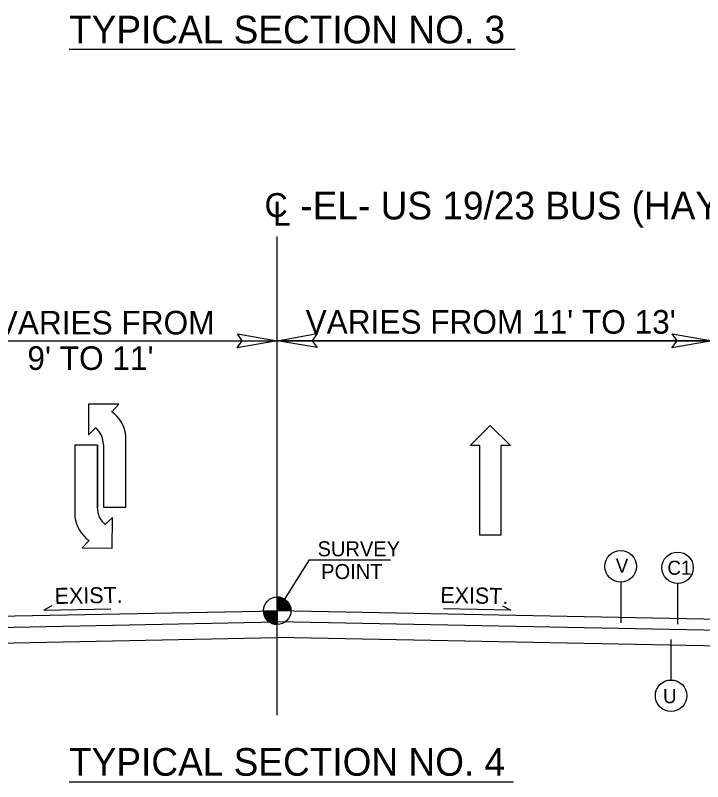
# Model space of a CAD drawing. Extents: x 1022283 to 1026986, y 174822 to 180471.
# Drawn here: x 1023630 to 1024096, y 178406 to 178925 of the extents above; entities that cross this region are included whole.
import ezdxf

# ---------------------------------------------------------------- set-up
doc = ezdxf.new("R2010")
doc.units = 0
for name, color, linetype in [('Default', 7, 'Continuous'), ('Prop Dimension', 7, 'Continuous'), ('Prop Lane Arrow CELL', 7, 'Continuous'), ('Prop Terminator CELL', 7, 'Continuous'), ('Typical Berm Information CELL', 7, 'Continuous'), ('Typical Grade Point Symbol CELL', 7, 'Continuous'), ('Typical ID Circle CELL', 7, 'Continuous'), ('Typical Text Centerline CELL', 7, 'Continuous'), ('Typical Text Grade Point CELL', 7, 'Continuous'), ('Typical Text ID Circle CELL', 7, 'Continuous'), ('Typical Text Label CELL', 7, 'Continuous')]:
    doc.layers.add(name, color=color, linetype=linetype)

# ---------------------------------------------------------------- blocks, each defined once
blk = doc.blocks.new('Lane Arrow Through')
at = {"layer": 'Prop Lane Arrow CELL'}
for p, q in [((-3.15, 1.6), (-3.15, 3.1)), ((-3.15, 3.1), (0, 0)), ((-17.15, 1.6), (-3.15, 1.6)), ((-17.15, -1.7), (-17.15, 1.6)), ((0, 0), (-3.15, -3.2)), ((-3.15, -1.7), (-17.15, -1.7)), ((-3.15, -3.2), (-3.15, -1.7))]:
    blk.add_line(p, q, dxfattribs=at)

msp = doc.modelspace()

# ---------------------------------------------------------------- linework, layer by layer
at = {"layer": 'Default'}
for p, q in [((1023299.79, 178705.04), (1023807.5, 178705.04)), ((1023807.5, 178705.04), (1024315.21, 178705.04)), ((1024315.21, 178705.04), (1023807.5, 178705.04))]:
    msp.add_line(p, q, dxfattribs=at)
at = {"layer": 'Prop Dimension'}
for p, q in [((1023807.5, 178716.15), (1023807.5, 178775.61)), ((1023807.5, 178451.35), (1023807.5, 178716.15)), ((1023829.15, 178556.58), (1023807.5, 178522.14)), ((1023829.15, 178556.58), (1023807.5, 178522.14)), ((1023299.79, 178511.99), (1023807.5, 178522.14)), ((1023299.79, 178511.99), (1023807.5, 178522.14)), ((1024315.21, 178511.99), (1023807.5, 178522.14)), ((1024315.21, 178511.99), (1023807.5, 178522.14)), ((1023299.79, 178504.49), (1023807.5, 178514.64)), ((1023299.79, 178504.49), (1023807.5, 178514.64)), ((1024315.21, 178504.49), (1023807.5, 178514.64)), ((1024315.21, 178504.49), (1023807.5, 178514.64)), ((1023299.79, 178493.9), (1023807.5, 178504.06)), ((1024315.21, 178493.9), (1023807.5, 178504.06))]:
    msp.add_line(p, q, dxfattribs=at)
at = {"layer": 'Prop Lane Arrow CELL'}
for p, q in [((1023700.21, 178662.05), (1023679.66, 178662.05)), ((1023679.66, 178662.05), (1023679.66, 178641.27)), ((1023695.37, 178656.97), (1023700.21, 178662.05)), ((1023679.66, 178641.27), (1023684.51, 178646.11)), ((1023705.06, 178592.32), (1023705.06, 178641.04)), ((1023670.43, 178634.34), (1023670.43, 178585.62)), ((1023685.67, 178634.34), (1023670.43, 178634.34)), ((1023685.67, 178592.09), (1023685.67, 178634.34)), ((1023685.67, 178634.34), (1023685.67, 178592.09)), ((1023689.82, 178634.57), (1023689.82, 178592.32)), ((1023689.82, 178592.32), (1023705.06, 178592.32)), ((1023695.83, 178585.39), (1023690.98, 178580.54)), ((1023695.6, 178564.61), (1023695.83, 178585.39)), ((1023680.13, 178569.69), (1023675.28, 178564.84)), ((1023675.28, 178564.84), (1023695.6, 178564.61))]:
    msp.add_line(p, q, dxfattribs=at)
for centre, radius, start, end in [((1023681.03, 178637.44), 24.26, 8.6761, 53.9878), ((1023674.65, 178634.68), 15.12, 360, 49.6582), ((1023700.71, 178592.04), 15.12, 180, 229.6582), ((1023694.33, 178589.28), 24.26, 188.6761, 233.9878)]:
    msp.add_arc(centre, radius, start, end, dxfattribs=at)
at = {"layer": 'Prop Terminator CELL'}
for points in [[(1023780.5, 178709.69), (1023807.5, 178705.04), (1023780.35, 178700.24), (1023783.8, 178705.04)], [(1023834.5, 178700.39), (1023807.5, 178705.04), (1023834.65, 178709.84), (1023831.2, 178705.04)], [(1023834.5, 178700.39), (1023807.5, 178705.04), (1023834.65, 178709.84), (1023831.2, 178705.04)], [(1024075.03, 178709.69), (1024102.03, 178705.04), (1024074.88, 178700.24), (1024078.33, 178705.04)]]:
    msp.add_lwpolyline(points, close=True, dxfattribs=at)
at = {"layer": 'Typical Berm Information CELL'}
for p, q in [((1023654.85, 178525.35), (1023649.33, 178522.59)), ((1023649.33, 178522.59), (1023694.85, 178523.5)), ((1023965.68, 178522.59), (1023920.16, 178523.5)), ((1023960.16, 178525.35), (1023965.68, 178522.59))]:
    msp.add_line(p, q, dxfattribs=at)
at = {"layer": 'Typical Grade Point Symbol CELL'}
for p, q in [((1023807.5, 178522.14), (1023807.5, 178531.44)), ((1023807.5, 178522.14), (1023807.5, 178531.44)), ((1023798.21, 178522.14), (1023807.5, 178522.14)), ((1023798.21, 178522.14), (1023807.5, 178522.14)), ((1023807.48, 178512.85), (1023807.5, 178522.14)), ((1023807.5, 178522.14), (1023807.48, 178512.85)), ((1023807.48, 178512.85), (1023807.5, 178522.14)), ((1023807.5, 178522.14), (1023807.48, 178512.85)), ((1023816.8, 178522.14), (1023807.5, 178522.14)), ((1023816.8, 178522.14), (1023807.5, 178522.14))]:
    msp.add_line(p, q, dxfattribs=at)
for points in [[(1023807.59, 178531.44), (1023807.59, 178531.44), (1023807.59, 178522.14)], [(1023807.59, 178531.44), (1023807.59, 178531.44), (1023807.59, 178522.14)], [(1023807.77, 178531.44), (1023807.77, 178522.14)], [(1023807.77, 178531.44), (1023807.77, 178522.14)], [(1023807.96, 178531.42), (1023807.96, 178522.14)], [(1023807.96, 178531.42), (1023807.96, 178522.14)], [(1023808.14, 178531.42), (1023808.14, 178522.14)], [(1023808.14, 178531.42), (1023808.14, 178522.14)], [(1023808.33, 178531.4), (1023808.33, 178522.14)], [(1023808.33, 178531.4), (1023808.33, 178522.14)], [(1023808.52, 178531.38), (1023808.52, 178522.14)], [(1023808.52, 178531.38), (1023808.52, 178522.14)], [(1023808.7, 178531.36), (1023808.7, 178522.14)], [(1023808.7, 178531.36), (1023808.7, 178522.14)], [(1023808.89, 178531.34), (1023808.89, 178522.14)], [(1023808.89, 178531.34), (1023808.89, 178522.14)], [(1023809.07, 178531.32), (1023809.07, 178522.14)], [(1023809.07, 178531.32), (1023809.07, 178522.14)], [(1023809.26, 178531.27), (1023809.26, 178522.14)], [(1023809.26, 178531.27), (1023809.26, 178522.14)], [(1023809.45, 178531.23), (1023809.45, 178522.14)], [(1023809.45, 178531.23), (1023809.45, 178522.14)], [(1023809.63, 178531.19), (1023809.63, 178522.14)], [(1023809.63, 178531.19), (1023809.63, 178522.14)], [(1023809.82, 178531.15), (1023809.82, 178522.14)], [(1023809.82, 178531.15), (1023809.82, 178522.14)], [(1023810, 178531.09), (1023810, 178522.14)], [(1023810, 178531.09), (1023810, 178522.14)], [(1023810.19, 178531.05), (1023810.19, 178522.14)], [(1023810.19, 178531.05), (1023810.19, 178522.14)], [(1023810.38, 178530.98), (1023810.38, 178522.14)], [(1023810.38, 178530.98), (1023810.38, 178522.14)], [(1023810.56, 178530.92), (1023810.56, 178522.14)], [(1023810.56, 178530.92), (1023810.56, 178522.14)], [(1023810.75, 178530.86), (1023810.75, 178522.14)], [(1023810.75, 178530.86), (1023810.75, 178522.14)], [(1023810.93, 178530.78), (1023810.93, 178522.14)], [(1023810.93, 178530.78), (1023810.93, 178522.14)], [(1023811.12, 178530.7), (1023811.12, 178522.14)], [(1023811.12, 178530.7), (1023811.12, 178522.14)], [(1023811.31, 178530.61), (1023811.31, 178522.14)], [(1023811.31, 178530.61), (1023811.31, 178522.14)], [(1023811.49, 178530.53), (1023811.49, 178522.14)], [(1023811.49, 178530.53), (1023811.49, 178522.14)], [(1023811.68, 178530.45), (1023811.68, 178522.14)], [(1023811.68, 178530.45), (1023811.68, 178522.14)], [(1023811.86, 178530.34), (1023811.86, 178522.14)], [(1023811.86, 178530.34), (1023811.86, 178522.14)], [(1023812.05, 178530.24), (1023812.05, 178522.14)], [(1023812.05, 178530.24), (1023812.05, 178522.14)], [(1023812.23, 178530.14), (1023812.23, 178522.14)], [(1023812.23, 178530.14), (1023812.23, 178522.14)], [(1023812.42, 178530.04), (1023812.42, 178522.14)], [(1023812.42, 178530.04), (1023812.42, 178522.14)], [(1023812.61, 178529.91), (1023812.61, 178522.14)], [(1023812.61, 178529.91), (1023812.61, 178522.14)], [(1023812.79, 178529.79), (1023812.79, 178522.14)], [(1023812.79, 178529.79), (1023812.79, 178522.14)], [(1023812.98, 178529.64), (1023812.98, 178522.14)], [(1023812.98, 178529.64), (1023812.98, 178522.14)], [(1023813.16, 178529.52), (1023813.16, 178522.14)], [(1023813.16, 178529.52), (1023813.16, 178522.14)], [(1023813.35, 178529.37), (1023813.35, 178522.14)], [(1023813.35, 178529.37), (1023813.35, 178522.14)], [(1023813.54, 178529.21), (1023813.54, 178522.14)], [(1023813.54, 178529.21), (1023813.54, 178522.14)], [(1023813.72, 178529.04), (1023813.72, 178522.14)], [(1023813.72, 178529.04), (1023813.72, 178522.14)], [(1023813.91, 178528.88), (1023813.91, 178522.14)], [(1023813.91, 178528.88), (1023813.91, 178522.14)], [(1023814.09, 178528.69), (1023814.09, 178522.14)], [(1023814.09, 178528.69), (1023814.09, 178522.14)], [(1023814.28, 178528.51), (1023814.28, 178522.14)], [(1023814.28, 178528.51), (1023814.28, 178522.14)], [(1023814.47, 178528.3), (1023814.47, 178522.14)], [(1023814.47, 178528.3), (1023814.47, 178522.14)], [(1023814.65, 178528.07), (1023814.65, 178522.14)], [(1023814.65, 178528.07), (1023814.65, 178522.14)], [(1023814.84, 178527.85), (1023814.84, 178522.14)], [(1023814.84, 178527.85), (1023814.84, 178522.14)], [(1023815.02, 178527.6), (1023815.02, 178522.14)], [(1023815.02, 178527.6), (1023815.02, 178522.14)], [(1023815.21, 178527.33), (1023815.21, 178522.14)], [(1023815.21, 178527.33), (1023815.21, 178522.14)], [(1023815.4, 178527.04), (1023815.4, 178522.14)], [(1023815.4, 178527.04), (1023815.4, 178522.14)], [(1023798.25, 178522.14), (1023798.25, 178521.13)], [(1023798.25, 178522.14), (1023798.25, 178521.13)], [(1023798.44, 178522.14), (1023798.44, 178520.04)], [(1023798.44, 178522.14), (1023798.44, 178520.04)], [(1023798.62, 178522.14), (1023798.62, 178519.38)], [(1023798.62, 178522.14), (1023798.62, 178519.38)], [(1023798.81, 178522.14), (1023798.81, 178518.82)], [(1023798.81, 178522.14), (1023798.81, 178518.82)], [(1023798.99, 178522.14), (1023798.99, 178518.38)], [(1023798.99, 178522.14), (1023798.99, 178518.38)], [(1023799.18, 178522.14), (1023799.18, 178517.99)], [(1023799.18, 178522.14), (1023799.18, 178517.99)], [(1023799.37, 178522.14), (1023799.37, 178517.64)], [(1023799.37, 178522.14), (1023799.37, 178517.64)], [(1023799.55, 178522.14), (1023799.55, 178517.31)], [(1023799.55, 178522.14), (1023799.55, 178517.31)], [(1023799.74, 178522.14), (1023799.74, 178517.02)], [(1023799.74, 178522.14), (1023799.74, 178517.02)], [(1023799.92, 178522.14), (1023799.92, 178516.75)], [(1023799.92, 178522.14), (1023799.92, 178516.75)], [(1023800.11, 178522.14), (1023800.11, 178516.5)], [(1023800.11, 178522.14), (1023800.11, 178516.5)], [(1023800.3, 178522.14), (1023800.3, 178516.28)], [(1023800.3, 178522.14), (1023800.3, 178516.28)], [(1023800.48, 178522.14), (1023800.48, 178516.05)], [(1023800.48, 178522.14), (1023800.48, 178516.05)], [(1023800.67, 178522.14), (1023800.67, 178515.84)], [(1023800.67, 178522.14), (1023800.67, 178515.84)], [(1023800.85, 178522.14), (1023800.85, 178515.64)], [(1023800.85, 178522.14), (1023800.85, 178515.64)], [(1023801.04, 178522.14), (1023801.04, 178515.45)], [(1023801.04, 178522.14), (1023801.04, 178515.45)], [(1023801.23, 178522.14), (1023801.23, 178515.29)], [(1023801.23, 178522.14), (1023801.23, 178515.29)], [(1023801.41, 178522.14), (1023801.41, 178515.12)], [(1023801.41, 178522.14), (1023801.41, 178515.12)], [(1023801.6, 178522.14), (1023801.6, 178514.96)], [(1023801.6, 178522.14), (1023801.6, 178514.96)], [(1023801.78, 178522.14), (1023801.78, 178514.81)], [(1023801.78, 178522.14), (1023801.78, 178514.81)], [(1023801.97, 178522.14), (1023801.97, 178514.67)], [(1023801.97, 178522.14), (1023801.97, 178514.67)], [(1023802.15, 178522.14), (1023802.15, 178514.54)], [(1023802.15, 178522.14), (1023802.15, 178514.54)], [(1023802.34, 178522.14), (1023802.34, 178514.42)], [(1023802.34, 178522.14), (1023802.34, 178514.42)], [(1023802.53, 178522.14), (1023802.53, 178514.29)], [(1023802.53, 178522.14), (1023802.53, 178514.29)], [(1023802.71, 178522.14), (1023802.71, 178514.17)], [(1023802.71, 178522.14), (1023802.71, 178514.17)], [(1023802.9, 178522.14), (1023802.9, 178514.07)], [(1023802.9, 178522.14), (1023802.9, 178514.07)], [(1023803.08, 178522.14), (1023803.08, 178513.96)], [(1023803.08, 178522.14), (1023803.08, 178513.96)], [(1023803.27, 178522.14), (1023803.27, 178513.86)], [(1023803.27, 178522.14), (1023803.27, 178513.86)], [(1023803.46, 178522.14), (1023803.46, 178513.78)], [(1023803.46, 178522.14), (1023803.46, 178513.78)], [(1023803.64, 178522.14), (1023803.64, 178513.7)], [(1023803.64, 178522.14), (1023803.64, 178513.7)], [(1023803.83, 178522.14), (1023803.83, 178513.61)], [(1023803.83, 178522.14), (1023803.83, 178513.61)], [(1023804.01, 178522.14), (1023804.01, 178513.53)], [(1023804.01, 178522.14), (1023804.01, 178513.53)], [(1023804.2, 178522.14), (1023804.2, 178513.45)], [(1023804.2, 178522.14), (1023804.2, 178513.45)], [(1023804.39, 178522.14), (1023804.39, 178513.39)], [(1023804.39, 178522.14), (1023804.39, 178513.39)], [(1023804.57, 178522.14), (1023804.57, 178513.32)], [(1023804.57, 178522.14), (1023804.57, 178513.32)], [(1023804.76, 178522.14), (1023804.76, 178513.26)], [(1023804.76, 178522.14), (1023804.76, 178513.26)], [(1023804.94, 178522.14), (1023804.94, 178513.22)], [(1023804.94, 178522.14), (1023804.94, 178513.22)], [(1023805.13, 178522.14), (1023805.13, 178513.16)], [(1023805.13, 178522.14), (1023805.13, 178513.16)], [(1023805.32, 178522.14), (1023805.32, 178513.12)], [(1023805.32, 178522.14), (1023805.32, 178513.12)], [(1023805.5, 178522.14), (1023805.5, 178513.08)], [(1023805.5, 178522.14), (1023805.5, 178513.08)], [(1023805.69, 178522.14), (1023805.69, 178513.03)], [(1023805.69, 178522.14), (1023805.69, 178513.03)], [(1023805.87, 178522.14), (1023805.87, 178512.99)], [(1023805.87, 178522.14), (1023805.87, 178512.99)], [(1023806.06, 178522.14), (1023806.06, 178512.97)], [(1023806.06, 178522.14), (1023806.06, 178512.97)], [(1023806.24, 178522.14), (1023806.24, 178512.93)], [(1023806.24, 178522.14), (1023806.24, 178512.93)], [(1023806.43, 178522.14), (1023806.43, 178512.91)], [(1023806.43, 178522.14), (1023806.43, 178512.91)], [(1023806.62, 178522.14), (1023806.62, 178512.89)], [(1023806.62, 178522.14), (1023806.62, 178512.89)], [(1023806.8, 178522.14), (1023806.8, 178512.87)], [(1023806.8, 178522.14), (1023806.8, 178512.87)], [(1023806.99, 178522.14), (1023806.99, 178512.87)], [(1023806.99, 178522.14), (1023806.99, 178512.87)], [(1023807.17, 178522.14), (1023807.17, 178512.85)], [(1023807.17, 178522.14), (1023807.17, 178512.85)], [(1023807.36, 178522.14), (1023807.36, 178512.85), (1023807.36, 178512.85)], [(1023807.36, 178522.14), (1023807.36, 178512.85), (1023807.36, 178512.85)], [(1023815.58, 178526.73), (1023815.58, 178522.14)], [(1023815.58, 178526.73), (1023815.58, 178522.14)], [(1023815.77, 178526.4), (1023815.77, 178522.14)], [(1023815.77, 178526.4), (1023815.77, 178522.14)], [(1023815.95, 178526.01), (1023815.95, 178522.14)], [(1023815.95, 178526.01), (1023815.95, 178522.14)], [(1023816.14, 178525.57), (1023816.14, 178522.14)], [(1023816.14, 178525.57), (1023816.14, 178522.14)], [(1023816.32, 178525.06), (1023816.32, 178522.14)], [(1023816.32, 178525.06), (1023816.32, 178522.14)], [(1023816.51, 178524.42), (1023816.51, 178522.14)], [(1023816.51, 178524.42), (1023816.51, 178522.14)], [(1023816.7, 178523.47), (1023816.7, 178522.14)], [(1023816.7, 178523.47), (1023816.7, 178522.14)]]:
    msp.add_lwpolyline(points, dxfattribs=at)
msp.add_circle((1023807.49, 178522.15), 9.3, dxfattribs=at)
msp.add_circle((1023807.49, 178522.15), 9.3, dxfattribs=at)
for start, end in [(359.9905, 89.9905), (359.9905, 89.9905), (179.9905, 269.9905), (179.9905, 269.9905)]:
    msp.add_arc((1023807.49, 178522.15), 9.3, start, end, dxfattribs=at)
at = {"layer": 'Typical ID Circle CELL'}
for p, q in [((1024040.15, 178541.54), (1024040.15, 178514.01)), ((1024078.68, 178540.58), (1024078.68, 178513.05)), ((1024074.27, 178475.21), (1024074.27, 178502.74))]:
    msp.add_line(p, q, dxfattribs=at)
for centre in [(1024040.15, 178552.19), (1024078.68, 178551.23), (1024074.27, 178464.56)]:
    msp.add_circle(centre, 10.65, dxfattribs=at)
at = {"layer": 'Typical Text Grade Point CELL'}
msp.add_line((1023829.15, 178556.58), (1023884.26, 178556.58), dxfattribs=at)
at = {"layer": 'Typical Text Label CELL'}
for p, q in [((1023666.49, 178902.44), (1023968.67, 178902.44)), ((1023666.49, 178406.34), (1023967.53, 178406.34))]:
    msp.add_line(p, q, dxfattribs=at)

# ---------------------------------------------------------------- block references
at = {"layer": 'Prop Lane Arrow CELL', "xscale": 4.329849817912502, "yscale": 4.329849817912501, "rotation": 90.00000000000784}
msp.add_blockref('Lane Arrow Through', (1023951.7, 178647.61), dxfattribs=at)
msp.add_blockref('Lane Arrow Through', (1023951.7, 178647.61), dxfattribs=at)

# ---------------------------------------------------------------- texts
at = {"layer": 'Prop Dimension'}
for s, height, p in [('-EL- US 19/23 BUS (HAYWOOD RD) ', 18.75, (1023823.22, 178787.21)), ('VARIES FROM', 16, (1023617.56, 178709.27)), ("VARIES FROM 11' TO 13'", 16, (1023826.73, 178709.8)), ("9' TO 11'", 16, (1023638.27, 178685.27))]:
    msp.add_text(s, height=height, dxfattribs=at).set_placement(p)
at = {"layer": 'Typical Berm Information CELL'}
for rotation, p in [(0.9927, (1023656.82, 178526.7)), (359.0073, (1023917.9, 178527.4))]:
    msp.add_text('EXIST.', height=10.873, rotation=rotation, dxfattribs=at).set_placement(p)
at = {"layer": 'Typical Text Centerline CELL'}
msp.add_text('C', height=16.22, dxfattribs=at).set_placement((1023798.92, 178788.81))
msp.add_text('L', height=16.22, rotation=359.9469, dxfattribs=at).set_placement((1023804.58, 178783))
at = {"layer": 'Typical Text Grade Point CELL'}
for s, p in [('SURVEY', (1023834.82, 178559.01)), ('POINT', (1023837.27, 178543.61))]:
    msp.add_text(s, height=10.163, dxfattribs=at).set_placement(p)
at = {"layer": 'Typical Text ID Circle CELL'}
for s, height, p in [('V', 9.53, (1024036.8, 178547.89)), ('C1', 9.534, (1024071.79, 178546.49)), ('U', 9.53, (1024068.82, 178459.5))]:
    msp.add_text(s, height=height, dxfattribs=at).set_placement(p)
at = {"layer": 'Typical Text Label CELL'}
for s, p in [('TYPICAL SECTION NO. 3', (1023666.49, 178906.44)), ('TYPICAL SECTION NO. 4', (1023666.49, 178410.34))]:
    msp.add_text(s, height=18.75, dxfattribs=at).set_placement(p)

doc.saveas('drawing.dxf')
